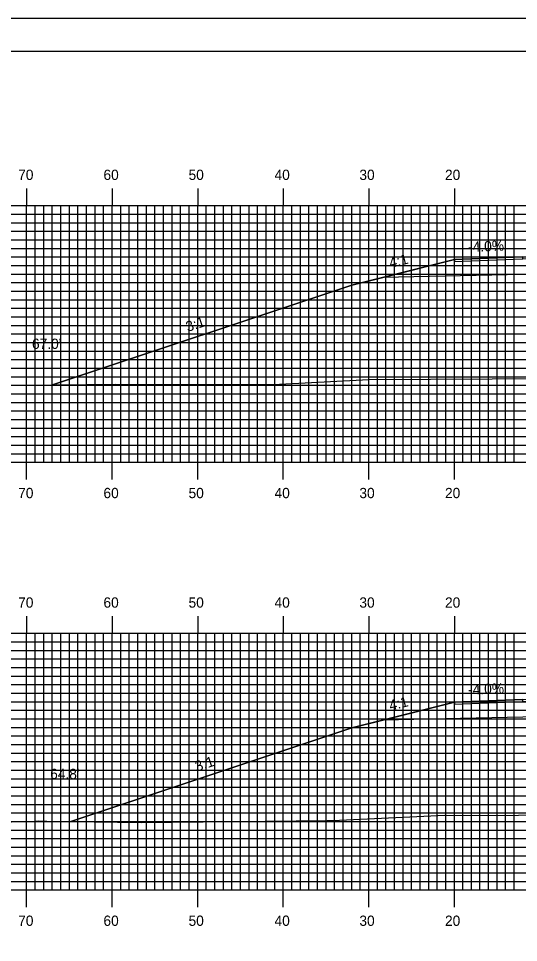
# Model space of a CAD drawing. Extents: x 1788550 to 1788893, y 442591 to 442811.
# Drawn here: x 1788644.7 to 1788703.1, y 442702.5 to 442810.5 of the extents above; entities that cross this region are included whole.
import ezdxf

# ---------------------------------------------------------------- set-up
doc = ezdxf.new("R2010")
doc.units = 0
for name, color, linetype in [('ANNOTATION', 7, 'Continuous'), ('BORDER', 7, 'Continuous'), ('D_Roadway_Centerline', 7, 'Continuous'), ('D_Roadway_Edge_Shoulder', 7, 'Continuous'), ('D_Roadway_SlopeLines', 7, 'Continuous'), ('D_Roadway_SubGrade', 7, 'Continuous'), ('D_Text_Standard', 7, 'Continuous'), ('H_V ANNOTATION', 7, 'Continuous'), ('MAJOR', 7, 'Continuous'), ('MINOR', 7, 'Continuous'), ('PLOT BOUNDARY', 7, 'Continuous'), ('S_Roadway_Centerline', 7, 'Continuous')]:
    doc.layers.add(name, color=color, linetype=linetype)

msp = doc.modelspace()

# ---------------------------------------------------------------- linework, layer by layer
at = {"layer": 'BORDER'}
msp.add_lwpolyline([(1788566.04, 442596.67), (1788886.04, 442596.67), (1788886.04, 442806.67), (1788566.04, 442806.67)], close=True, dxfattribs=at)
at = {"layer": 'D_Roadway_Centerline'}
for points in [[(1788648.65, 442767.71), (1788683.64, 442779.37), (1788687.28, 442780.28), (1788695.64, 442782.37), (1788703.64, 442782.69), (1788715.64, 442782.96), (1788727.64, 442783.22), (1788735.64, 442782.9), (1788744.01, 442780.81), (1788747.64, 442779.9), (1788777.18, 442770.05)], [(1788650.8, 442716.68), (1788683.64, 442727.62), (1788687.28, 442728.53), (1788695.64, 442730.62), (1788703.64, 442730.94), (1788715.64, 442731.21), (1788727.64, 442731.47), (1788735.64, 442731.15), (1788744.01, 442729.06), (1788747.64, 442728.15), (1788775.7, 442718.8)]]:
    msp.add_lwpolyline(points, dxfattribs=at)
at = {"layer": 'D_Roadway_Edge_Shoulder'}
for points in [[(1788703.64, 442782.69), (1788695.64, 442782.37), (1788695.64, 442782.12), (1788703.64, 442782.44)], [(1788703.64, 442730.94), (1788695.64, 442730.62), (1788695.64, 442730.37), (1788703.64, 442730.69)]]:
    msp.add_lwpolyline(points, close=True, dxfattribs=at)
at = {"layer": 'D_Roadway_SlopeLines'}
for points in [[(1788695.64, 442782.37), (1788683.64, 442779.37), (1788648.65, 442767.71)], [(1788695.64, 442730.62), (1788683.64, 442727.62), (1788650.8, 442716.68)]]:
    msp.add_lwpolyline(points, dxfattribs=at)
at = {"layer": 'D_Roadway_SubGrade'}
for points in [[(1788703.64, 442780.61), (1788687.28, 442780.28), (1788695.64, 442782.37), (1788695.64, 442782.12), (1788703.64, 442782.44), (1788715.64, 442782.71), (1788727.64, 442782.97), (1788735.64, 442782.65), (1788735.64, 442782.9), (1788744.01, 442780.81), (1788727.64, 442781.14), (1788715.64, 442780.87)], [(1788703.64, 442728.86), (1788687.28, 442728.53), (1788695.64, 442730.62), (1788695.64, 442730.37), (1788703.64, 442730.69), (1788715.64, 442730.96), (1788727.64, 442731.22), (1788735.64, 442730.9), (1788735.64, 442731.15), (1788744.01, 442729.06), (1788727.64, 442729.39), (1788715.64, 442729.12)]]:
    msp.add_lwpolyline(points, close=True, dxfattribs=at)
at = {"layer": 'MAJOR'}
for p, q in [((1788645.64, 442790.67), (1788645.64, 442788.67)), ((1788655.64, 442790.67), (1788655.64, 442788.67)), ((1788665.64, 442790.67), (1788665.64, 442788.67)), ((1788675.64, 442790.67), (1788675.64, 442788.67)), ((1788685.64, 442790.67), (1788685.64, 442788.67)), ((1788695.64, 442790.67), (1788695.64, 442788.67)), ((1788575.64, 442788.67), (1788855.64, 442788.67)), ((1788575.64, 442788.67), (1788855.64, 442788.67)), ((1788645.64, 442758.67), (1788645.64, 442788.67)), ((1788655.64, 442758.67), (1788655.64, 442788.67)), ((1788665.64, 442758.67), (1788665.64, 442788.67)), ((1788675.64, 442758.67), (1788675.64, 442788.67)), ((1788685.64, 442758.67), (1788685.64, 442788.67)), ((1788695.64, 442758.67), (1788695.64, 442788.67)), ((1788575.64, 442783.67), (1788855.64, 442783.67)), ((1788575.64, 442778.67), (1788855.64, 442778.67)), ((1788575.64, 442773.67), (1788855.64, 442773.67)), ((1788575.64, 442768.67), (1788855.64, 442768.67)), ((1788575.64, 442763.67), (1788855.64, 442763.67)), ((1788575.64, 442758.67), (1788855.64, 442758.67)), ((1788575.64, 442758.67), (1788855.64, 442758.67)), ((1788645.64, 442756.66), (1788645.64, 442758.67)), ((1788655.64, 442756.66), (1788655.64, 442758.67)), ((1788665.64, 442756.66), (1788665.64, 442758.67)), ((1788675.64, 442756.66), (1788675.64, 442758.67)), ((1788685.64, 442756.66), (1788685.64, 442758.67)), ((1788695.64, 442756.66), (1788695.64, 442758.67)), ((1788645.64, 442740.67), (1788645.64, 442738.67)), ((1788655.64, 442740.67), (1788655.64, 442738.67)), ((1788665.64, 442740.67), (1788665.64, 442738.67)), ((1788675.64, 442740.67), (1788675.64, 442738.67)), ((1788685.64, 442740.67), (1788685.64, 442738.67)), ((1788695.64, 442740.67), (1788695.64, 442738.67)), ((1788575.64, 442738.67), (1788855.64, 442738.67)), ((1788575.64, 442738.67), (1788855.64, 442738.67)), ((1788645.64, 442708.67), (1788645.64, 442738.67)), ((1788655.64, 442708.67), (1788655.64, 442738.67)), ((1788665.64, 442708.67), (1788665.64, 442738.67)), ((1788675.64, 442708.67), (1788675.64, 442738.67)), ((1788685.64, 442708.67), (1788685.64, 442738.67)), ((1788695.64, 442708.67), (1788695.64, 442738.67)), ((1788575.64, 442733.67), (1788855.64, 442733.67)), ((1788575.64, 442728.67), (1788855.64, 442728.67)), ((1788575.64, 442723.67), (1788855.64, 442723.67)), ((1788575.64, 442718.67), (1788855.64, 442718.67)), ((1788575.64, 442713.67), (1788855.64, 442713.67)), ((1788575.64, 442708.67), (1788855.64, 442708.67)), ((1788575.64, 442708.67), (1788855.64, 442708.67)), ((1788645.64, 442706.66), (1788645.64, 442708.67)), ((1788655.64, 442706.66), (1788655.64, 442708.67)), ((1788665.64, 442706.66), (1788665.64, 442708.67)), ((1788675.64, 442706.66), (1788675.64, 442708.67)), ((1788685.64, 442706.66), (1788685.64, 442708.67)), ((1788695.64, 442706.66), (1788695.64, 442708.67))]:
    msp.add_line(p, q, dxfattribs=at)
at = {"layer": 'MINOR'}
for p, q in [((1788646.64, 442758.67), (1788646.64, 442788.67)), ((1788647.64, 442758.67), (1788647.64, 442788.67)), ((1788648.64, 442758.67), (1788648.64, 442788.67)), ((1788649.64, 442758.67), (1788649.64, 442788.67)), ((1788650.64, 442758.67), (1788650.64, 442788.67)), ((1788651.64, 442758.67), (1788651.64, 442788.67)), ((1788652.64, 442758.67), (1788652.64, 442788.67)), ((1788653.64, 442758.67), (1788653.64, 442788.67)), ((1788654.64, 442758.67), (1788654.64, 442788.67)), ((1788656.64, 442758.67), (1788656.64, 442788.67)), ((1788657.64, 442758.67), (1788657.64, 442788.67)), ((1788658.64, 442758.67), (1788658.64, 442788.67)), ((1788659.64, 442758.67), (1788659.64, 442788.67)), ((1788660.64, 442758.67), (1788660.64, 442788.67)), ((1788661.64, 442758.67), (1788661.64, 442788.67)), ((1788662.64, 442758.67), (1788662.64, 442788.67)), ((1788663.64, 442758.67), (1788663.64, 442788.67)), ((1788664.64, 442758.67), (1788664.64, 442788.67)), ((1788666.64, 442758.67), (1788666.64, 442788.67)), ((1788667.64, 442758.67), (1788667.64, 442788.67)), ((1788668.64, 442758.67), (1788668.64, 442788.67)), ((1788669.64, 442758.67), (1788669.64, 442788.67)), ((1788670.64, 442758.67), (1788670.64, 442788.67)), ((1788671.64, 442758.67), (1788671.64, 442788.67)), ((1788672.64, 442758.67), (1788672.64, 442788.67)), ((1788673.64, 442758.67), (1788673.64, 442788.67)), ((1788674.64, 442758.67), (1788674.64, 442788.67)), ((1788676.64, 442758.67), (1788676.64, 442788.67)), ((1788677.64, 442758.67), (1788677.64, 442788.67)), ((1788678.64, 442758.67), (1788678.64, 442788.67)), ((1788679.64, 442758.67), (1788679.64, 442788.67)), ((1788680.64, 442758.67), (1788680.64, 442788.67)), ((1788681.64, 442758.67), (1788681.64, 442788.67)), ((1788682.64, 442758.67), (1788682.64, 442788.67)), ((1788683.64, 442758.67), (1788683.64, 442788.67)), ((1788684.64, 442758.67), (1788684.64, 442788.67)), ((1788686.64, 442758.67), (1788686.64, 442788.67)), ((1788687.64, 442758.67), (1788687.64, 442788.67)), ((1788688.64, 442758.67), (1788688.64, 442788.67)), ((1788689.64, 442758.67), (1788689.64, 442788.67)), ((1788690.64, 442758.67), (1788690.64, 442788.67)), ((1788691.64, 442758.67), (1788691.64, 442788.67)), ((1788692.64, 442758.67), (1788692.64, 442788.67)), ((1788693.64, 442758.67), (1788693.64, 442788.67)), ((1788694.64, 442758.67), (1788694.64, 442788.67)), ((1788696.64, 442758.67), (1788696.64, 442788.67)), ((1788697.64, 442758.67), (1788697.64, 442788.67)), ((1788698.64, 442758.67), (1788698.64, 442788.67)), ((1788699.64, 442758.67), (1788699.64, 442788.67)), ((1788700.64, 442758.67), (1788700.64, 442788.67)), ((1788701.64, 442758.67), (1788701.64, 442788.67)), ((1788702.64, 442758.67), (1788702.64, 442788.67)), ((1788575.64, 442787.67), (1788855.64, 442787.67)), ((1788575.64, 442786.67), (1788855.64, 442786.67)), ((1788575.64, 442785.67), (1788855.64, 442785.67)), ((1788575.64, 442784.67), (1788855.64, 442784.67)), ((1788575.64, 442782.67), (1788855.64, 442782.67)), ((1788575.64, 442781.67), (1788855.64, 442781.67)), ((1788575.64, 442780.67), (1788855.64, 442780.67)), ((1788575.64, 442779.67), (1788855.64, 442779.67)), ((1788575.64, 442777.67), (1788855.64, 442777.67)), ((1788575.64, 442776.67), (1788855.64, 442776.67)), ((1788575.64, 442775.67), (1788855.64, 442775.67)), ((1788575.64, 442774.67), (1788855.64, 442774.67)), ((1788575.64, 442772.67), (1788855.64, 442772.67)), ((1788575.64, 442771.67), (1788855.64, 442771.67)), ((1788575.64, 442770.67), (1788855.64, 442770.67)), ((1788575.64, 442769.67), (1788855.64, 442769.67)), ((1788575.64, 442767.67), (1788855.64, 442767.67)), ((1788575.64, 442766.67), (1788855.64, 442766.67)), ((1788575.64, 442765.67), (1788855.64, 442765.67)), ((1788575.64, 442764.67), (1788855.64, 442764.67)), ((1788575.64, 442762.67), (1788855.64, 442762.67)), ((1788575.64, 442761.67), (1788855.64, 442761.67)), ((1788575.64, 442760.67), (1788855.64, 442760.67)), ((1788575.64, 442759.67), (1788855.64, 442759.67)), ((1788646.64, 442708.67), (1788646.64, 442738.67)), ((1788647.64, 442708.67), (1788647.64, 442738.67)), ((1788648.64, 442708.67), (1788648.64, 442738.67)), ((1788649.64, 442708.67), (1788649.64, 442738.67)), ((1788650.64, 442708.67), (1788650.64, 442738.67)), ((1788651.64, 442708.67), (1788651.64, 442738.67)), ((1788652.64, 442708.67), (1788652.64, 442738.67)), ((1788653.64, 442708.67), (1788653.64, 442738.67)), ((1788654.64, 442708.67), (1788654.64, 442738.67)), ((1788656.64, 442708.67), (1788656.64, 442738.67)), ((1788657.64, 442708.67), (1788657.64, 442738.67)), ((1788658.64, 442708.67), (1788658.64, 442738.67)), ((1788659.64, 442708.67), (1788659.64, 442738.67)), ((1788660.64, 442708.67), (1788660.64, 442738.67)), ((1788661.64, 442708.67), (1788661.64, 442738.67)), ((1788662.64, 442708.67), (1788662.64, 442738.67)), ((1788663.64, 442708.67), (1788663.64, 442738.67)), ((1788664.64, 442708.67), (1788664.64, 442738.67)), ((1788666.64, 442708.67), (1788666.64, 442738.67)), ((1788667.64, 442708.67), (1788667.64, 442738.67)), ((1788668.64, 442708.67), (1788668.64, 442738.67)), ((1788669.64, 442708.67), (1788669.64, 442738.67)), ((1788670.64, 442708.67), (1788670.64, 442738.67)), ((1788671.64, 442708.67), (1788671.64, 442738.67)), ((1788672.64, 442708.67), (1788672.64, 442738.67)), ((1788673.64, 442708.67), (1788673.64, 442738.67)), ((1788674.64, 442708.67), (1788674.64, 442738.67)), ((1788676.64, 442708.67), (1788676.64, 442738.67)), ((1788677.64, 442708.67), (1788677.64, 442738.67)), ((1788678.64, 442708.67), (1788678.64, 442738.67)), ((1788679.64, 442708.67), (1788679.64, 442738.67)), ((1788680.64, 442708.67), (1788680.64, 442738.67)), ((1788681.64, 442708.67), (1788681.64, 442738.67)), ((1788682.64, 442708.67), (1788682.64, 442738.67)), ((1788683.64, 442708.67), (1788683.64, 442738.67)), ((1788684.64, 442708.67), (1788684.64, 442738.67)), ((1788686.64, 442708.67), (1788686.64, 442738.67)), ((1788687.64, 442708.67), (1788687.64, 442738.67)), ((1788688.64, 442708.67), (1788688.64, 442738.67)), ((1788689.64, 442708.67), (1788689.64, 442738.67)), ((1788690.64, 442708.67), (1788690.64, 442738.67)), ((1788691.64, 442708.67), (1788691.64, 442738.67)), ((1788692.64, 442708.67), (1788692.64, 442738.67)), ((1788693.64, 442708.67), (1788693.64, 442738.67)), ((1788694.64, 442708.67), (1788694.64, 442738.67)), ((1788696.64, 442708.67), (1788696.64, 442738.67)), ((1788697.64, 442708.67), (1788697.64, 442738.67)), ((1788698.64, 442708.67), (1788698.64, 442738.67)), ((1788699.64, 442708.67), (1788699.64, 442738.67)), ((1788700.64, 442708.67), (1788700.64, 442738.67)), ((1788701.64, 442708.67), (1788701.64, 442738.67)), ((1788702.64, 442708.67), (1788702.64, 442738.67)), ((1788575.64, 442737.67), (1788855.64, 442737.67)), ((1788575.64, 442736.67), (1788855.64, 442736.67)), ((1788575.64, 442735.67), (1788855.64, 442735.67)), ((1788575.64, 442734.67), (1788855.64, 442734.67)), ((1788575.64, 442732.67), (1788855.64, 442732.67)), ((1788575.64, 442731.67), (1788855.64, 442731.67)), ((1788575.64, 442730.67), (1788855.64, 442730.67)), ((1788575.64, 442729.67), (1788855.64, 442729.67)), ((1788575.64, 442727.67), (1788855.64, 442727.67)), ((1788575.64, 442726.67), (1788855.64, 442726.67)), ((1788575.64, 442725.67), (1788855.64, 442725.67)), ((1788575.64, 442724.67), (1788855.64, 442724.67)), ((1788575.64, 442722.67), (1788855.64, 442722.67)), ((1788575.64, 442721.67), (1788855.64, 442721.67)), ((1788575.64, 442720.67), (1788855.64, 442720.67)), ((1788575.64, 442719.67), (1788855.64, 442719.67)), ((1788575.64, 442717.67), (1788855.64, 442717.67)), ((1788575.64, 442716.67), (1788855.64, 442716.67)), ((1788575.64, 442715.67), (1788855.64, 442715.67)), ((1788575.64, 442714.67), (1788855.64, 442714.67)), ((1788575.64, 442712.67), (1788855.64, 442712.67)), ((1788575.64, 442711.67), (1788855.64, 442711.67)), ((1788575.64, 442710.67), (1788855.64, 442710.67)), ((1788575.64, 442709.67), (1788855.64, 442709.67))]:
    msp.add_line(p, q, dxfattribs=at)
at = {"layer": 'PLOT BOUNDARY'}
msp.add_lwpolyline([(1788549.86, 442590.55), (1788889.86, 442590.55), (1788889.86, 442810.55), (1788549.86, 442810.55)], close=True, dxfattribs=at)
at = {"layer": 'S_Roadway_Centerline'}
for points in [[(1788642.05, 442767.65), (1788656.06, 442767.78), (1788673.18, 442767.74), (1788674.07, 442767.74), (1788674.48, 442767.75), (1788685.66, 442768.33), (1788707.29, 442768.47), (1788712.28, 442768.56), (1788722.36, 442768.91), (1788730.17, 442769), (1788742.69, 442769.18), (1788746.62, 442769.2), (1788748.9, 442769.21), (1788758.93, 442769.02), (1788767.17, 442769.73), (1788777.92, 442770.08)], [(1788634.38, 442716.37), (1788646.55, 442716.72), (1788647.07, 442716.73), (1788647.99, 442716.72), (1788659.01, 442716.55), (1788680.79, 442716.78), (1788681.7, 442716.78), (1788682.22, 442716.84), (1788694.54, 442717.42), (1788701.6, 442717.37), (1788707.85, 442717.51), (1788718.22, 442717.76), (1788718.97, 442717.78), (1788731.54, 442718.28), (1788738.36, 442718.41), (1788743.31, 442718.47), (1788754.29, 442718.93), (1788755.61, 442718.98), (1788756.19, 442718.99), (1788756.94, 442718.99), (1788775.56, 442718.79), (1788791.23, 442719.32)]]:
    msp.add_lwpolyline(points, dxfattribs=at)

# ---------------------------------------------------------------- texts
at = {"layer": 'ANNOTATION'}
for s, rotation, p in [('-4.0%', 2.2906, (1788697.28, 442783.24)), ('4:1', 14.0362, (1788688.18, 442781.37)), ('3:1', 18.4348, (1788664.48, 442773.9)), ('-4.0%', 2.2906, (1788697.28, 442731.49)), ('4:1', 14.0362, (1788688.18, 442729.62)), ('3:1', 18.4348, (1788665.56, 442722.5))]:
    msp.add_text(s, height=1.2, rotation=rotation, dxfattribs=at).set_placement(p)
at = {"layer": 'D_Text_Standard'}
for s, p in [("67.0'", (1788646.27, 442771.92)), ("64.8'", (1788648.39, 442721.63))]:
    msp.add_text(s, height=1.2, dxfattribs=at).set_placement(p)
at = {"layer": 'H_V ANNOTATION'}
for s, p in [('70', (1788644.65, 442791.67)), ('60', (1788654.62, 442791.67)), ('50', (1788664.57, 442791.67)), ('40', (1788674.62, 442791.67)), ('30', (1788684.54, 442791.67)), ('20', (1788694.55, 442791.67)), ('70', (1788644.65, 442754.47)), ('60', (1788654.62, 442754.47)), ('50', (1788664.57, 442754.47)), ('40', (1788674.62, 442754.47)), ('30', (1788684.54, 442754.47)), ('20', (1788694.55, 442754.47)), ('70', (1788644.65, 442741.67)), ('60', (1788654.62, 442741.67)), ('50', (1788664.57, 442741.67)), ('40', (1788674.62, 442741.67)), ('30', (1788684.54, 442741.67)), ('20', (1788694.55, 442741.67)), ('70', (1788644.65, 442704.47)), ('60', (1788654.62, 442704.47)), ('50', (1788664.57, 442704.47)), ('40', (1788674.62, 442704.47)), ('30', (1788684.54, 442704.47)), ('20', (1788694.55, 442704.47))]:
    msp.add_text(s, height=1.2, dxfattribs=at).set_placement(p)

doc.saveas('drawing.dxf')
